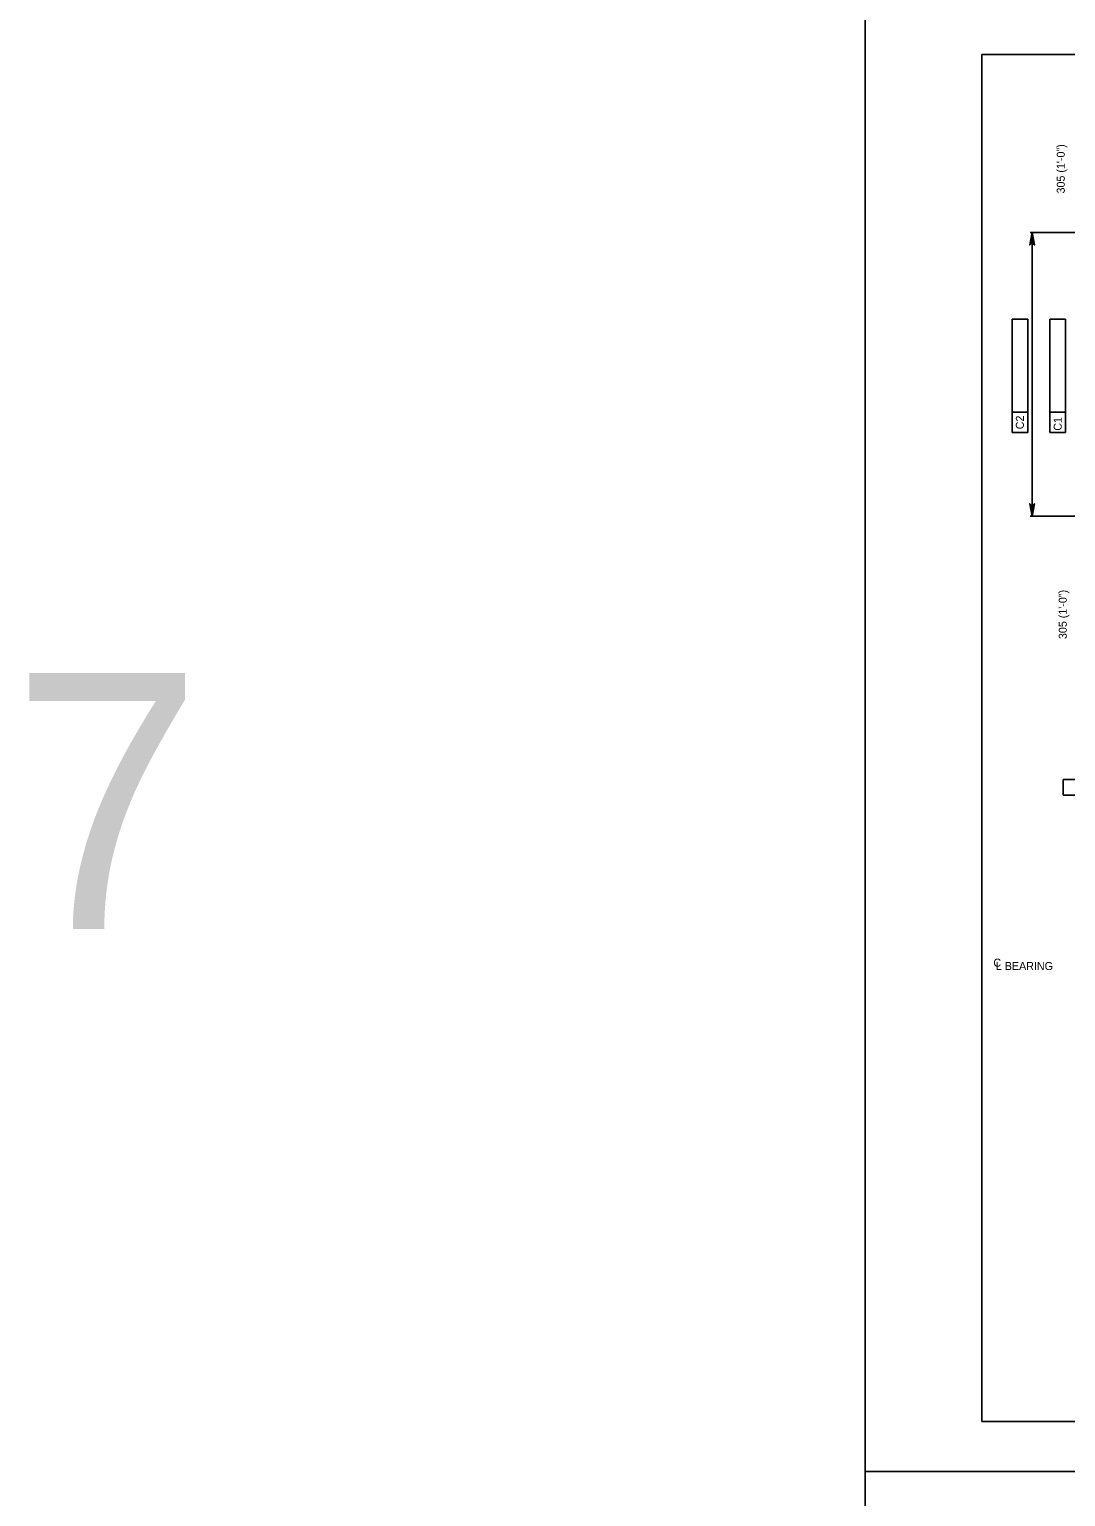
# Model space of a CAD drawing. Extents: x -13 to 81, y -176 to 0.
# Drawn here: x -12.53 to 3.01, y -154.38 to -132.38 of the extents above; entities that cross this region are included whole.
import ezdxf

# ---------------------------------------------------------------- set-up
doc = ezdxf.new("R2010")
doc.units = 0
for name, color, linetype in [('Level 1', 7, 'Continuous'), ('Level 4', 7, 'Continuous'), ('Level 62', 7, 'Continuous'), ('Level 63', 7, 'Continuous')]:
    doc.layers.add(name, color=color, linetype=linetype)

msp = doc.modelspace()

# ---------------------------------------------------------------- linework, layer by layer
at = {"layer": 'Level 1'}
msp.add_lwpolyline([(1.75, -153.25), (33.25, -153.25), (33.25, -132.75), (1.75, -132.75)], close=True, dxfattribs=at)
at = {"layer": 'Level 4'}
for p, q in [((7.218, -135.421), (2.473, -135.421)), ((2.502, -135.421), (2.502, -139.673)), ((2.438, -136.718), (2.202, -136.718)), ((2.202, -138.116), (2.202, -136.718)), ((2.438, -138.419), (2.438, -136.718)), ((3.005, -136.718), (2.769, -136.718)), ((2.769, -138.116), (2.769, -136.718)), ((3.005, -138.419), (3.005, -136.718)), ((2.202, -138.419), (2.202, -138.116)), ((2.438, -138.116), (2.202, -138.116)), ((2.769, -138.419), (2.769, -138.116)), ((3.005, -138.116), (2.769, -138.116)), ((2.202, -138.419), (2.438, -138.419)), ((2.769, -138.419), (3.005, -138.419)), ((7.218, -139.673), (2.473, -139.673)), ((2.971, -143.621), (4.671, -143.621)), ((2.971, -143.621), (2.971, -143.857)), ((2.971, -143.857), (4.671, -143.857))]:
    msp.add_line(p, q, dxfattribs=at)
for points in [[(2.502, -135.421), (2.537, -135.608), (2.527, -135.594), (2.515, -135.586), (2.502, -135.584), (2.49, -135.586), (2.477, -135.594), (2.467, -135.608), (2.502, -135.421), (2.477, -135.594), (2.49, -135.586), (2.502, -135.421), (2.502, -135.584), (2.515, -135.586), (2.502, -135.421), (2.527, -135.594)], [(2.502, -139.673), (2.467, -139.487), (2.477, -139.501), (2.49, -139.509), (2.502, -139.511), (2.515, -139.509), (2.527, -139.501), (2.537, -139.487), (2.502, -139.673), (2.527, -139.501), (2.515, -139.509), (2.502, -139.673), (2.502, -139.511), (2.49, -139.509), (2.502, -139.673), (2.477, -139.501)]]:
    msp.add_lwpolyline(points, dxfattribs=at)
at = {"layer": 'Level 62'}
msp.add_line((0, -154), (0, -154), dxfattribs=at)
at = {"layer": 'Level 63'}
for points in [[(0, -154), (34, -154), (34, -132), (0, -132)], [(0, -176), (34, -176), (34, -154), (0, -154)]]:
    msp.add_lwpolyline(points, close=True, dxfattribs=at)

# ---------------------------------------------------------------- texts
at = {"layer": 'Level 4'}
for s, rotation, p in [('305 (1\'-0")', 90, (2.993, -134.836)), ('C2', 89.9382, (2.38, -138.371)), ('C1', 89.9382, (2.947, -138.393)), ('305 (1\'-0")', 90, (3.023, -141.517))]:
    msp.add_text(s, height=0.12, rotation=rotation, dxfattribs=at).set_placement(p)
for s, height, p in [('7', 3.84, (-12.793, -145.866)), ('C', 0.12, (1.923, -146.429)), ('L BEARING', 0.12, (1.96, -146.479))]:
    msp.add_text(s, height=height, dxfattribs=at).set_placement(p)

doc.saveas('drawing.dxf')
